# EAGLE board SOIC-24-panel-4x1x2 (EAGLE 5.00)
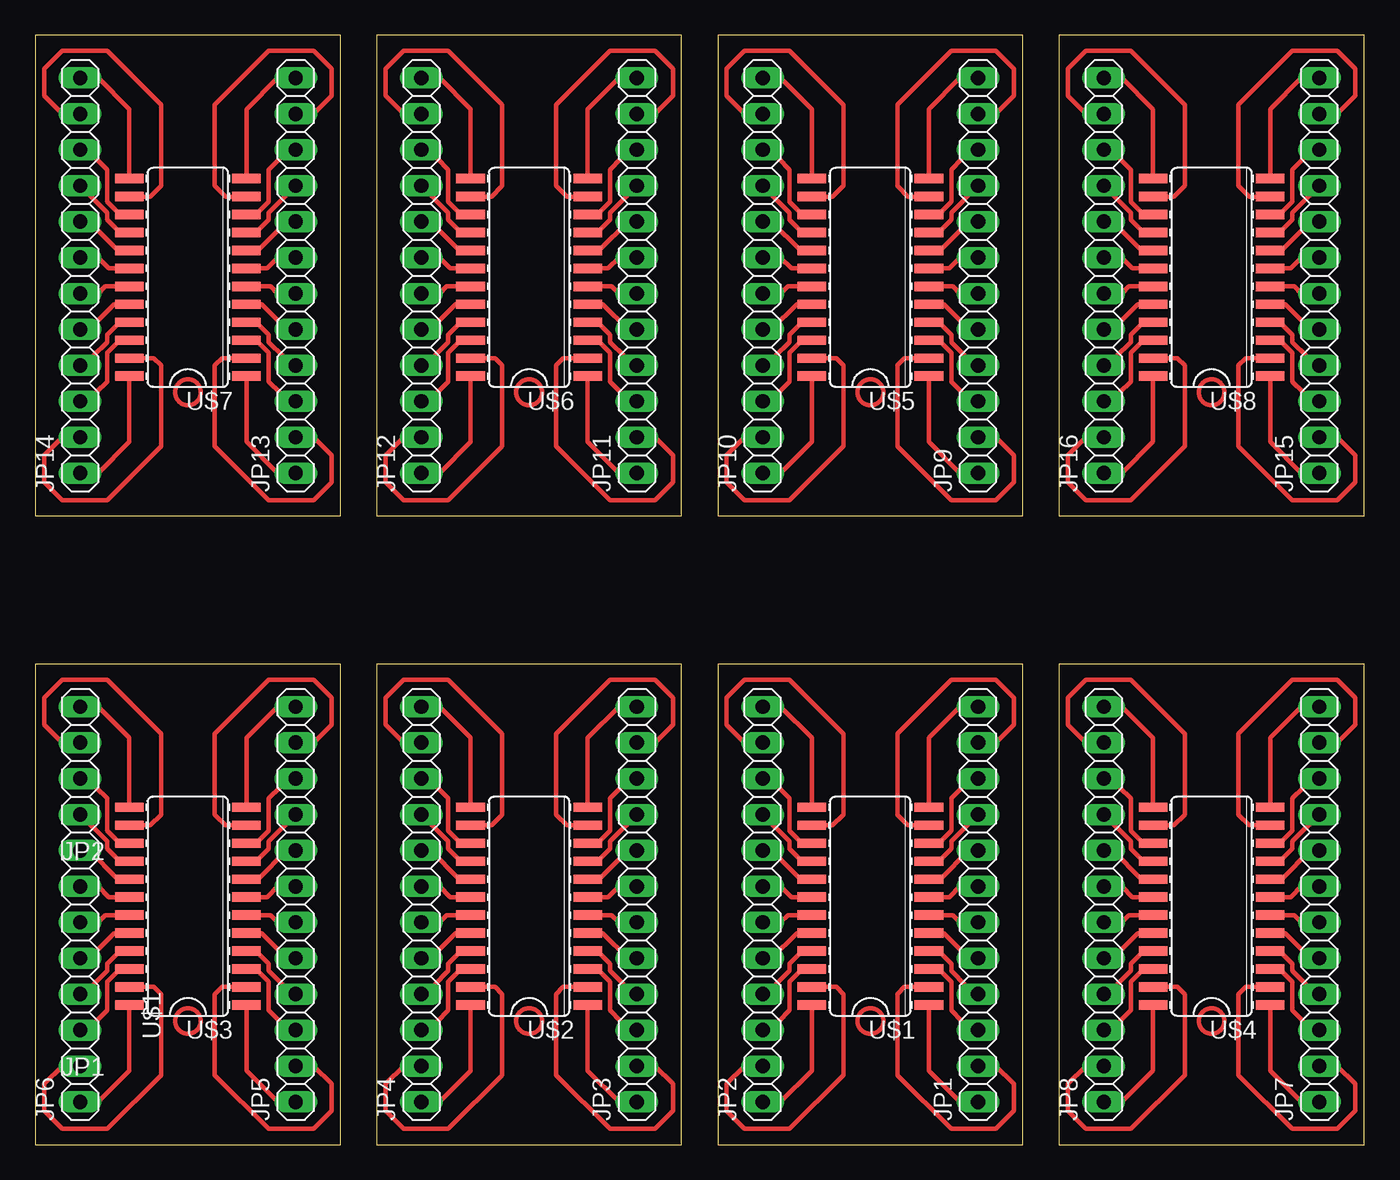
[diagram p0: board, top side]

Size 93.97 x 78.41 mm. Coordinates in mm from the lower left corner, seen from the top.
Outline: 69.84,0 69.84,33.96 48.26,33.96 48.26,0 69.84,0
Outline: 45.71,0 45.71,33.96 24.13,33.96 24.13,0 45.71,0
Outline: 21.58,0 21.58,33.96 0,33.96 0,0 21.58,0
Outline: 93.97,0 93.97,33.96 72.39,33.96 72.39,0 93.97,0
Outline: 69.84,44.45 69.84,78.41 48.26,78.41 48.26,44.45 69.84,44.45
Outline: 45.71,44.45 45.71,78.41 24.13,78.41 24.13,44.45 45.71,44.45
Outline: 21.58,44.45 21.58,78.41 0,78.41 0,44.45 21.58,44.45
Outline: 93.97,44.45 93.97,78.41 72.39,78.41 72.39,44.45 93.97,44.45
Copper layers (1*16): Top 0.035mm / dielectric 1.5mm / Bottom 0.035mm
Design rules "default": minimum track width 10mil, minimum drill 24mil, track to track 8mil, track to pad 8mil, pad to pad 8mil, via to via 8mil, smd to smd 8mil, copper to edge 40mil, drill to drill 8mil, minimum pad ring 10mil, minimum via ring 8mil, stop-mask expansion 4mil, vias tented up to drill 0mil, thermal gap 10mil

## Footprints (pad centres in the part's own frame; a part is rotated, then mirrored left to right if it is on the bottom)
1X12 = drill 1.016 long: 1 -13.97,0; 2 -11.43,0; 3 -8.89,0; 4 -6.35,0; 5 -3.81,0; 6 -1.27,0; 7 1.27,0; 8 3.81,0; 9 6.35,0; 10 8.89,0; 11 11.43,0; 12 13.97,0
SOIC-24 = smd 0.66 x 2.032: 1 -6.985,-4.14; 2 -5.715,-4.14; 3 -4.445,-4.14; 4 -3.175,-4.14; 5 -1.905,-4.14; 6 -0.635,-4.14; 7 0.635,-4.14; 8 1.905,-4.14; 9 3.175,-4.14; 10 4.445,-4.14; 11 5.715,-4.14; 12 6.985,-4.14; 13 6.985,4.14; 14 5.715,4.14; 15 4.445,4.14; 16 3.175,4.14; 17 1.905,4.14; 18 0.635,4.14; 19 -0.635,4.14; 20 -1.905,4.14; 21 -3.175,4.14; 22 -4.445,4.14; 23 -5.715,4.14; 24 -6.985,4.14

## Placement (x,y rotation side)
JP1  [1X12]  66.67,16.98 90 top
JP2  [1X12]  51.43,16.98 90 top
JP3  [1X12]  42.54,16.98 90 top
JP4  [1X12]  27.3,16.98 90 top
JP5  [1X12]  18.41,16.98 90 top
JP6  [1X12]  3.17,16.98 90 top
JP7  [1X12]  90.8,16.98 90 top
JP8  [1X12]  75.56,16.98 90 top
JP9  [1X12]  66.67,61.43 90 top
JP10  [1X12]  51.43,61.43 90 top
JP11  [1X12]  42.54,61.43 90 top
JP12  [1X12]  27.3,61.43 90 top
JP13  [1X12]  18.41,61.43 90 top
JP14  [1X12]  3.17,61.43 90 top
JP15  [1X12]  90.8,61.43 90 top
JP16  [1X12]  75.56,61.43 90 top
U$1  SOIC-24  [SOIC-24]  59.05,16.85 90 top
U$2  SOIC-24  [SOIC-24]  34.92,16.85 90 top
U$3  SOIC-24  [SOIC-24]  10.79,16.85 90 top
U$4  SOIC-24  [SOIC-24]  83.18,16.85 90 top
U$5  SOIC-24  [SOIC-24]  59.05,61.3 90 top
U$6  SOIC-24  [SOIC-24]  34.92,61.3 90 top
U$7  SOIC-24  [SOIC-24]  10.79,61.3 90 top
U$8  SOIC-24  [SOIC-24]  83.18,61.3 90 top

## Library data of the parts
JP1-JP16 = pinhead
U$1-U$8 = smd

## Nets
N$1: JP1.1 U$1.1
N$2: JP1.2 U$1.2
N$3: JP1.3 U$1.3
N$4: JP1.4 U$1.4
N$5: JP1.5 U$1.5
N$6: JP1.6 U$1.6
N$7: JP1.7 U$1.7
N$8: JP1.8 U$1.8
N$9: JP1.9 U$1.9
N$10: JP1.10 U$1.10
N$11: JP1.11 U$1.11
N$12: JP1.12 U$1.12
N$13: JP2.1 U$1.24
N$14: JP2.2 U$1.23
N$15: JP2.3 U$1.22
N$16: JP2.4 U$1.21
N$17: JP2.5 U$1.20
N$18: JP2.6 U$1.19
N$19: JP2.7 U$1.18
N$20: JP2.8 U$1.17
N$21: JP2.9 U$1.16
N$22: JP2.10 U$1.15
N$23: JP2.11 U$1.14
N$24: JP2.12 U$1.13
N$25: JP3.1 U$2.1
N$26: JP3.2 U$2.2
N$27: JP3.3 U$2.3
N$28: JP3.4 U$2.4
N$29: JP3.5 U$2.5
N$30: JP3.6 U$2.6
N$31: JP3.7 U$2.7
N$32: JP3.8 U$2.8
N$33: JP3.9 U$2.9
N$34: JP3.10 U$2.10
N$35: JP3.11 U$2.11
N$36: JP3.12 U$2.12
N$37: JP4.1 U$2.24
N$38: JP4.2 U$2.23
N$39: JP4.3 U$2.22
N$40: JP4.4 U$2.21
N$41: JP4.5 U$2.20
N$42: JP4.6 U$2.19
N$43: JP4.7 U$2.18
N$44: JP4.8 U$2.17
N$45: JP4.9 U$2.16
N$46: JP4.10 U$2.15
N$47: JP4.11 U$2.14
N$48: JP4.12 U$2.13
N$49: JP5.1 U$3.1
N$50: JP5.2 U$3.2
N$51: JP5.3 U$3.3
N$52: JP5.4 U$3.4
N$53: JP5.5 U$3.5
N$54: JP5.6 U$3.6
N$55: JP5.7 U$3.7
N$56: JP5.8 U$3.8
N$57: JP5.9 U$3.9
N$58: JP5.10 U$3.10
N$59: JP5.11 U$3.11
N$60: JP5.12 U$3.12
N$61: JP6.1 U$3.24
N$62: JP6.2 U$3.23
N$63: JP6.3 U$3.22
N$64: JP6.4 U$3.21
N$65: JP6.5 U$3.20
N$66: JP6.6 U$3.19
N$67: JP6.7 U$3.18
N$68: JP6.8 U$3.17
N$69: JP6.9 U$3.16
N$70: JP6.10 U$3.15
N$71: JP6.11 U$3.14
N$72: JP6.12 U$3.13
N$73: JP7.1 U$4.1
N$74: JP7.2 U$4.2
N$75: JP7.3 U$4.3
N$76: JP7.4 U$4.4
N$77: JP7.5 U$4.5
N$78: JP7.6 U$4.6
N$79: JP7.7 U$4.7
N$80: JP7.8 U$4.8
N$81: JP7.9 U$4.9
N$82: JP7.10 U$4.10
N$83: JP7.11 U$4.11
N$84: JP7.12 U$4.12
N$85: JP8.1 U$4.24
N$86: JP8.2 U$4.23
N$87: JP8.3 U$4.22
N$88: JP8.4 U$4.21
N$89: JP8.5 U$4.20
N$90: JP8.6 U$4.19
N$91: JP8.7 U$4.18
N$92: JP8.8 U$4.17
N$93: JP8.9 U$4.16
N$94: JP8.10 U$4.15
N$95: JP8.11 U$4.14
N$96: JP8.12 U$4.13
N$97: JP9.1 U$5.1
N$98: JP9.2 U$5.2
N$99: JP9.3 U$5.3
N$100: JP9.4 U$5.4
N$101: JP9.5 U$5.5
N$102: JP9.6 U$5.6
N$103: JP9.7 U$5.7
N$104: JP9.8 U$5.8
N$105: JP9.9 U$5.9
N$106: JP9.10 U$5.10
N$107: JP9.11 U$5.11
N$108: JP9.12 U$5.12
N$109: JP10.1 U$5.24
N$110: JP10.2 U$5.23
N$111: JP10.3 U$5.22
N$112: JP10.4 U$5.21
N$113: JP10.5 U$5.20
N$114: JP10.6 U$5.19
N$115: JP10.7 U$5.18
N$116: JP10.8 U$5.17
N$117: JP10.9 U$5.16
N$118: JP10.10 U$5.15
N$119: JP10.11 U$5.14
N$120: JP10.12 U$5.13
N$121: JP11.1 U$6.1
N$122: JP11.2 U$6.2
N$123: JP11.3 U$6.3
N$124: JP11.4 U$6.4
N$125: JP11.5 U$6.5
N$126: JP11.6 U$6.6
N$127: JP11.7 U$6.7
N$128: JP11.8 U$6.8
N$129: JP11.9 U$6.9
N$130: JP11.10 U$6.10
N$131: JP11.11 U$6.11
N$132: JP11.12 U$6.12
N$133: JP12.1 U$6.24
N$134: JP12.2 U$6.23
N$135: JP12.3 U$6.22
N$136: JP12.4 U$6.21
N$137: JP12.5 U$6.20
N$138: JP12.6 U$6.19
N$139: JP12.7 U$6.18
N$140: JP12.8 U$6.17
N$141: JP12.9 U$6.16
N$142: JP12.10 U$6.15
N$143: JP12.11 U$6.14
N$144: JP12.12 U$6.13
N$145: JP13.1 U$7.1
N$146: JP13.2 U$7.2
N$147: JP13.3 U$7.3
N$148: JP13.4 U$7.4
N$149: JP13.5 U$7.5
N$150: JP13.6 U$7.6
N$151: JP13.7 U$7.7
N$152: JP13.8 U$7.8
N$153: JP13.9 U$7.9
N$154: JP13.10 U$7.10
N$155: JP13.11 U$7.11
N$156: JP13.12 U$7.12
N$157: JP14.1 U$7.24
N$158: JP14.2 U$7.23
N$159: JP14.3 U$7.22
N$160: JP14.4 U$7.21
N$161: JP14.5 U$7.20
N$162: JP14.6 U$7.19
N$163: JP14.7 U$7.18
N$164: JP14.8 U$7.17
N$165: JP14.9 U$7.16
N$166: JP14.10 U$7.15
N$167: JP14.11 U$7.14
N$168: JP14.12 U$7.13
N$169: JP15.1 U$8.1
N$170: JP15.2 U$8.2
N$171: JP15.3 U$8.3
N$172: JP15.4 U$8.4
N$173: JP15.5 U$8.5
N$174: JP15.6 U$8.6
N$175: JP15.7 U$8.7
N$176: JP15.8 U$8.8
N$177: JP15.9 U$8.9
N$178: JP15.10 U$8.10
N$179: JP15.11 U$8.11
N$180: JP15.12 U$8.12
N$181: JP16.1 U$8.24
N$182: JP16.2 U$8.23
N$183: JP16.3 U$8.22
N$184: JP16.4 U$8.21
N$185: JP16.5 U$8.20
N$186: JP16.6 U$8.19
N$187: JP16.7 U$8.18
N$188: JP16.8 U$8.17
N$189: JP16.9 U$8.16
N$190: JP16.10 U$8.15
N$191: JP16.11 U$8.14
N$192: JP16.12 U$8.13

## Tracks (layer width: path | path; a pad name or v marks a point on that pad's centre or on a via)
N$1
  Top 0.305: U$1.1 63.19,5.22 65.4,3.01 JP1.1
N$2
  Top 0.305: U$1.2 61.46,11.14 60.96,10.63 60.96,4.92 64.77,1.1 67.94,1.1 69.21,2.38 69.21,4.28 67.94,5.55 JP1.2
N$3
  Top 0.254: 64.13,12.15 U$1.3
  Top 0.305: 64.13,12.15 64.77,11.52 64.77,9.49 65.53,8.73 JP1.3
N$4
  Top 0.254: 64.13,13.42 U$1.4
  Top 0.305: 64.13,13.42 64.77,12.79 64.77,12.28 65.78,11.27 JP1.4
N$5
  Top 0.305: U$1.5 64.26,14.95 66.03,13.17 JP1.5
N$6
  Top 0.305: U$1.6 64.89,16.22 65.4,15.71 JP1.6
N$7
  Top 0.305: U$1.7 64.64,17.49 65.4,18.25 JP1.7
N$8
  Top 0.305: 64,18.76 66.03,20.79 JP1.8
  Top 0.406: U$1.8 64,18.76
N$9
  Top 0.254: U$1.9 64.13,20.28
  Top 0.305: 64.13,20.28 64.77,20.92 64.77,21.42 JP1.9
N$10
  Top 0.254: 64.13,21.55 U$1.10
  Top 0.305: 64.13,21.55 64.77,22.19 64.77,24.47 65.53,25.23 JP1.10
N$11
  Top 0.305: U$1.11 61.72,22.57 60.96,23.33 60.96,29.04 64.77,32.85 67.94,32.85 69.21,31.58 69.21,29.68 67.94,28.41 JP1.11
N$12
  Top 0.305: U$1.12 63.19,28.74 65.4,30.95 JP1.12
N$13
  Top 0.305: U$1.24 54.91,5.22 52.7,3.01 JP2.1
N$14
  Top 0.305: U$1.23 56.64,11.14 57.15,10.63 57.15,4.92 53.34,1.1 50.16,1.1 48.89,2.38 48.89,4.28 50.16,5.55 JP2.2
N$15
  Top 0.254: U$1.22 53.97,12.15
  Top 0.305: 53.97,12.15 53.34,11.52 53.34,9.49 52.57,8.73 JP2.3
N$16
  Top 0.254: U$1.21 53.97,13.42
  Top 0.305: 53.97,13.42 53.34,12.79 53.34,12.28 52.32,11.27 JP2.4
N$17
  Top 0.305: U$1.20 53.84,14.95 52.07,13.17 JP2.5
N$18
  Top 0.305: U$1.19 53.21,16.22 52.7,15.71 JP2.6
N$19
  Top 0.305: U$1.18 53.46,17.49 52.7,18.25 JP2.7
N$20
  Top 0.305: U$1.17 54.1,18.76 52.07,20.79 JP2.8
N$21
  Top 0.254: U$1.16 53.97,20.28
  Top 0.305: 53.97,20.28 53.34,20.92 53.34,21.42 JP2.9
N$22
  Top 0.254: U$1.15 53.97,21.55
  Top 0.305: 53.97,21.55 53.34,22.19 53.34,24.47 52.57,25.23 JP2.10
N$23
  Top 0.305: U$1.14 56.38,22.57 57.15,23.33 57.15,29.04 53.34,32.85 50.16,32.85 48.89,31.58 48.89,29.68 50.16,28.41
  Top 0.406: 50.16,28.41 JP2.11
N$24
  Top 0.305: U$1.13 54.91,28.74 52.7,30.95 JP2.12
N$25
  Top 0.305: U$2.1 39.06,5.22 41.27,3.01 JP3.1
N$26
  Top 0.305: U$2.2 37.33,11.14 36.83,10.63 36.83,4.92 40.64,1.1 43.81,1.1 45.08,2.38 45.08,4.28 43.81,5.55 JP3.2
N$27
  Top 0.254: 40,12.15 U$2.3
  Top 0.305: 40,12.15 40.64,11.52 40.64,9.49 41.4,8.73 JP3.3
N$28
  Top 0.254: 40,13.42 U$2.4
  Top 0.305: 40,13.42 40.64,12.79 40.64,12.28 41.65,11.27 JP3.4
N$29
  Top 0.305: U$2.5 40.13,14.95 41.91,13.17 JP3.5
N$30
  Top 0.305: U$2.6 40.76,16.22 41.27,15.71 JP3.6
N$31
  Top 0.305: U$2.7 40.51,17.49 41.27,18.25 JP3.7
N$32
  Top 0.305: 39.87,18.76 41.91,20.79 JP3.8
  Top 0.406: U$2.8 39.87,18.76
N$33
  Top 0.254: U$2.9 40,20.28
  Top 0.305: 40,20.28 40.64,20.92 40.64,21.42 JP3.9
N$34
  Top 0.254: 40,21.55 U$2.10
  Top 0.305: 40,21.55 40.64,22.19 40.64,24.47 41.4,25.23 JP3.10
N$35
  Top 0.305: U$2.11 37.59,22.57 36.83,23.33 36.83,29.04 40.64,32.85 43.81,32.85 45.08,31.58 45.08,29.68 43.81,28.41 JP3.11
N$36
  Top 0.305: U$2.12 39.06,28.74 41.27,30.95 JP3.12
N$37
  Top 0.305: U$2.24 30.78,5.22 28.57,3.01 JP4.1
N$38
  Top 0.305: U$2.23 32.51,11.14 33.02,10.63 33.02,4.92 29.2,1.1 26.03,1.1 24.76,2.38 24.76,4.28 26.03,5.55 JP4.2
N$39
  Top 0.254: U$2.22 29.84,12.15
  Top 0.305: 29.84,12.15 29.2,11.52 29.2,9.49 28.44,8.73 JP4.3
N$40
  Top 0.254: U$2.21 29.84,13.42
  Top 0.305: 29.84,13.42 29.2,12.79 29.2,12.28 28.19,11.27 JP4.4
N$41
  Top 0.305: U$2.20 29.71,14.95 27.93,13.17 JP4.5
N$42
  Top 0.305: U$2.19 29.08,16.22 28.57,15.71 JP4.6
N$43
  Top 0.305: U$2.18 29.33,17.49 28.57,18.25 JP4.7
N$44
  Top 0.305: U$2.17 29.97,18.76 27.93,20.79 JP4.8
N$45
  Top 0.254: U$2.16 29.84,20.28
  Top 0.305: 29.84,20.28 29.2,20.92 29.2,21.42 JP4.9
N$46
  Top 0.254: U$2.15 29.84,21.55
  Top 0.305: 29.84,21.55 29.2,22.19 29.2,24.47 28.44,25.23 JP4.10
N$47
  Top 0.305: U$2.14 32.25,22.57 33.02,23.33 33.02,29.04 29.2,32.85 26.03,32.85 24.76,31.58 24.76,29.68 26.03,28.41
  Top 0.406: 26.03,28.41 JP4.11
N$48
  Top 0.305: U$2.13 30.78,28.74 28.57,30.95 JP4.12
N$49
  Top 0.305: U$3.1 14.93,5.22 17.14,3.01 JP5.1
N$50
  Top 0.305: U$3.2 13.2,11.14 12.7,10.63 12.7,4.92 16.5,1.1 19.68,1.1 20.95,2.38 20.95,4.28 19.68,5.55 JP5.2
N$51
  Top 0.254: 15.87,12.15 U$3.3
  Top 0.305: 15.87,12.15 16.5,11.52 16.5,9.49 17.27,8.73 JP5.3
N$52
  Top 0.254: 15.87,13.42 U$3.4
  Top 0.305: 15.87,13.42 16.5,12.79 16.5,12.28 17.52,11.27 JP5.4
N$53
  Top 0.305: U$3.5 16,14.95 17.77,13.17 JP5.5
N$54
  Top 0.305: U$3.6 16.63,16.22 17.14,15.71 JP5.6
N$55
  Top 0.305: U$3.7 16.38,17.49 17.14,18.25 JP5.7
N$56
  Top 0.305: 15.74,18.76 17.77,20.79 JP5.8
  Top 0.406: U$3.8 15.74,18.76
N$57
  Top 0.254: U$3.9 15.87,20.28
  Top 0.305: 15.87,20.28 16.5,20.92 16.5,21.42 JP5.9
N$58
  Top 0.254: 15.87,21.55 U$3.10
  Top 0.305: 15.87,21.55 16.5,22.19 16.5,24.47 17.27,25.23 JP5.10
N$59
  Top 0.305: U$3.11 13.46,22.57 12.7,23.33 12.7,29.04 16.5,32.85 19.68,32.85 20.95,31.58 20.95,29.68 19.68,28.41 JP5.11
N$60
  Top 0.305: U$3.12 14.93,28.74 17.14,30.95 JP5.12
N$61
  Top 0.305: U$3.24 6.65,5.22 4.44,3.01 JP6.1
N$62
  Top 0.305: U$3.23 8.38,11.14 8.89,10.63 8.89,4.92 5.08,1.1 1.9,1.1 0.63,2.38 0.63,4.28 1.9,5.55 JP6.2
N$63
  Top 0.254: U$3.22 5.71,12.15
  Top 0.305: 5.71,12.15 5.08,11.52 5.08,9.49 4.31,8.73 JP6.3
N$64
  Top 0.254: U$3.21 5.71,13.42
  Top 0.305: 5.71,13.42 5.08,12.79 5.08,12.28 4.06,11.27 JP6.4
N$65
  Top 0.305: U$3.20 5.58,14.95 3.8,13.17 JP6.5
N$66
  Top 0.305: U$3.19 4.95,16.22 4.44,15.71 JP6.6
N$67
  Top 0.305: U$3.18 5.2,17.49 4.44,18.25 JP6.7
N$68
  Top 0.305: U$3.17 5.84,18.76 3.8,20.79 JP6.8
N$69
  Top 0.254: U$3.16 5.71,20.28
  Top 0.305: 5.71,20.28 5.08,20.92 5.08,21.42 JP6.9
N$70
  Top 0.254: U$3.15 5.71,21.55
  Top 0.305: 5.71,21.55 5.08,22.19 5.08,24.47 4.31,25.23 JP6.10
N$71
  Top 0.305: U$3.14 8.12,22.57 8.89,23.33 8.89,29.04 5.08,32.85 1.9,32.85 0.63,31.58 0.63,29.68 1.9,28.41
  Top 0.406: 1.9,28.41 JP6.11
N$72
  Top 0.305: U$3.13 6.65,28.74 4.44,30.95 JP6.12
N$73
  Top 0.305: U$4.1 87.32,5.22 89.53,3.01 JP7.1
N$74
  Top 0.305: U$4.2 85.59,11.14 85.08,10.63 85.08,4.92 88.89,1.1 92.07,1.1 93.34,2.38 93.34,4.28 92.07,5.55 JP7.2
N$75
  Top 0.254: 88.26,12.15 U$4.3
  Top 0.305: 88.26,12.15 88.89,11.52 88.89,9.49 89.66,8.73 JP7.3
N$76
  Top 0.254: 88.26,13.42 U$4.4
  Top 0.305: 88.26,13.42 88.89,12.79 88.89,12.28 89.91,11.27 JP7.4
N$77
  Top 0.305: U$4.5 88.39,14.95 90.16,13.17 JP7.5
N$78
  Top 0.305: U$4.6 89.02,16.22 89.53,15.71 JP7.6
N$79
  Top 0.305: U$4.7 88.77,17.49 89.53,18.25 JP7.7
N$80
  Top 0.305: 88.13,18.76 90.16,20.79 JP7.8
  Top 0.406: U$4.8 88.13,18.76
N$81
  Top 0.254: U$4.9 88.26,20.28
  Top 0.305: 88.26,20.28 88.89,20.92 88.89,21.42 JP7.9
N$82
  Top 0.254: 88.26,21.55 U$4.10
  Top 0.305: 88.26,21.55 88.89,22.19 88.89,24.47 89.66,25.23 JP7.10
N$83
  Top 0.305: U$4.11 85.85,22.57 85.08,23.33 85.08,29.04 88.89,32.85 92.07,32.85 93.34,31.58 93.34,29.68 92.07,28.41 JP7.11
N$84
  Top 0.305: U$4.12 87.32,28.74 89.53,30.95 JP7.12
N$85
  Top 0.305: U$4.24 79.04,5.22 76.83,3.01 JP8.1
N$86
  Top 0.305: U$4.23 80.77,11.14 81.27,10.63 81.27,4.92 77.46,1.1 74.29,1.1 73.02,2.38 73.02,4.28 74.29,5.55 JP8.2
N$87
  Top 0.254: U$4.22 78.1,12.15
  Top 0.305: 78.1,12.15 77.46,11.52 77.46,9.49 76.7,8.73 JP8.3
N$88
  Top 0.254: U$4.21 78.1,13.42
  Top 0.305: 78.1,13.42 77.46,12.79 77.46,12.28 76.45,11.27 JP8.4
N$89
  Top 0.305: U$4.20 77.97,14.95 76.19,13.17 JP8.5
N$90
  Top 0.305: U$4.19 77.34,16.22 76.83,15.71 JP8.6
N$91
  Top 0.305: U$4.18 77.59,17.49 76.83,18.25 JP8.7
N$92
  Top 0.305: U$4.17 78.23,18.76 76.19,20.79 JP8.8
N$93
  Top 0.254: U$4.16 78.1,20.28
  Top 0.305: 78.1,20.28 77.46,20.92 77.46,21.42 JP8.9
N$94
  Top 0.254: U$4.15 78.1,21.55
  Top 0.305: 78.1,21.55 77.46,22.19 77.46,24.47 76.7,25.23 JP8.10
N$95
  Top 0.305: U$4.14 80.51,22.57 81.27,23.33 81.27,29.04 77.46,32.85 74.29,32.85 73.02,31.58 73.02,29.68 74.29,28.41
  Top 0.406: 74.29,28.41 JP8.11
N$96
  Top 0.305: U$4.13 79.04,28.74 76.83,30.95 JP8.12
N$97
  Top 0.305: U$5.1 63.19,49.67 65.4,47.46 JP9.1
N$98
  Top 0.305: U$5.2 61.46,55.59 60.96,55.08 60.96,49.37 64.77,45.55 67.94,45.55 69.21,46.82 69.21,48.73 67.94,50 JP9.2
N$99
  Top 0.254: 64.13,56.6 U$5.3
  Top 0.305: 64.13,56.6 64.77,55.97 64.77,53.94 65.53,53.17 JP9.3
N$100
  Top 0.254: 64.13,57.87 U$5.4
  Top 0.305: 64.13,57.87 64.77,57.24 64.77,56.73 65.78,55.71 JP9.4
N$101
  Top 0.305: U$5.5 64.26,59.4 66.03,57.62 JP9.5
N$102
  Top 0.305: U$5.6 64.89,60.67 65.4,60.16 JP9.6
N$103
  Top 0.305: U$5.7 64.64,61.94 65.4,62.7 JP9.7
N$104
  Top 0.305: 64,63.21 66.03,65.24 JP9.8
  Top 0.406: U$5.8 64,63.21
N$105
  Top 0.254: U$5.9 64.13,64.73
  Top 0.305: 64.13,64.73 64.77,65.37 64.77,65.88 JP9.9
N$106
  Top 0.254: 64.13,66 U$5.10
  Top 0.305: 64.13,66 64.77,66.64 64.77,68.92 65.53,69.69 JP9.10
N$107
  Top 0.305: U$5.11 61.72,67.02 60.96,67.78 60.96,73.5 64.77,77.3 67.94,77.3 69.21,76.03 69.21,74.13 67.94,72.86 JP9.11
N$108
  Top 0.305: U$5.12 63.19,73.19 65.4,75.4 JP9.12
N$109
  Top 0.305: U$5.24 54.91,49.67 52.7,47.46 JP10.1
N$110
  Top 0.305: U$5.23 56.64,55.59 57.15,55.08 57.15,49.37 53.34,45.55 50.16,45.55 48.89,46.82 48.89,48.73 50.16,50 JP10.2
N$111
  Top 0.254: U$5.22 53.97,56.6
  Top 0.305: 53.97,56.6 53.34,55.97 53.34,53.94 52.57,53.17 JP10.3
N$112
  Top 0.254: U$5.21 53.97,57.87
  Top 0.305: 53.97,57.87 53.34,57.24 53.34,56.73 52.32,55.71 JP10.4
N$113
  Top 0.305: U$5.20 53.84,59.4 52.07,57.62 JP10.5
N$114
  Top 0.305: U$5.19 53.21,60.67 52.7,60.16 JP10.6
N$115
  Top 0.305: U$5.18 53.46,61.94 52.7,62.7 JP10.7
N$116
  Top 0.305: U$5.17 54.1,63.21 52.07,65.24 JP10.8
N$117
  Top 0.254: U$5.16 53.97,64.73
  Top 0.305: 53.97,64.73 53.34,65.37 53.34,65.88 JP10.9
N$118
  Top 0.254: U$5.15 53.97,66
  Top 0.305: 53.97,66 53.34,66.64 53.34,68.92 52.57,69.69 JP10.10
N$119
  Top 0.305: U$5.14 56.38,67.02 57.15,67.78 57.15,73.5 53.34,77.3 50.16,77.3 48.89,76.03 48.89,74.13 50.16,72.86
  Top 0.406: 50.16,72.86 JP10.11
N$120
  Top 0.305: U$5.13 54.91,73.19 52.7,75.4 JP10.12
N$121
  Top 0.305: U$6.1 39.06,49.67 41.27,47.46 JP11.1
N$122
  Top 0.305: U$6.2 37.33,55.59 36.83,55.08 36.83,49.37 40.64,45.55 43.81,45.55 45.08,46.82 45.08,48.73 43.81,50 JP11.2
N$123
  Top 0.254: 40,56.6 U$6.3
  Top 0.305: 40,56.6 40.64,55.97 40.64,53.94 41.4,53.17 JP11.3
N$124
  Top 0.254: 40,57.87 U$6.4
  Top 0.305: 40,57.87 40.64,57.24 40.64,56.73 41.65,55.71 JP11.4
N$125
  Top 0.305: U$6.5 40.13,59.4 41.91,57.62 JP11.5
N$126
  Top 0.305: U$6.6 40.76,60.67 41.27,60.16 JP11.6
N$127
  Top 0.305: U$6.7 40.51,61.94 41.27,62.7 JP11.7
N$128
  Top 0.305: 39.87,63.21 41.91,65.24 JP11.8
  Top 0.406: U$6.8 39.87,63.21
N$129
  Top 0.254: U$6.9 40,64.73
  Top 0.305: 40,64.73 40.64,65.37 40.64,65.88 JP11.9
N$130
  Top 0.254: 40,66 U$6.10
  Top 0.305: 40,66 40.64,66.64 40.64,68.92 41.4,69.69 JP11.10
N$131
  Top 0.305: U$6.11 37.59,67.02 36.83,67.78 36.83,73.5 40.64,77.3 43.81,77.3 45.08,76.03 45.08,74.13 43.81,72.86 JP11.11
N$132
  Top 0.305: U$6.12 39.06,73.19 41.27,75.4 JP11.12
N$133
  Top 0.305: U$6.24 30.78,49.67 28.57,47.46 JP12.1
N$134
  Top 0.305: U$6.23 32.51,55.59 33.02,55.08 33.02,49.37 29.2,45.55 26.03,45.55 24.76,46.82 24.76,48.73 26.03,50 JP12.2
N$135
  Top 0.254: U$6.22 29.84,56.6
  Top 0.305: 29.84,56.6 29.2,55.97 29.2,53.94 28.44,53.17 JP12.3
N$136
  Top 0.254: U$6.21 29.84,57.87
  Top 0.305: 29.84,57.87 29.2,57.24 29.2,56.73 28.19,55.71 JP12.4
N$137
  Top 0.305: U$6.20 29.71,59.4 27.93,57.62 JP12.5
N$138
  Top 0.305: U$6.19 29.08,60.67 28.57,60.16 JP12.6
N$139
  Top 0.305: U$6.18 29.33,61.94 28.57,62.7 JP12.7
N$140
  Top 0.305: U$6.17 29.97,63.21 27.93,65.24 JP12.8
N$141
  Top 0.254: U$6.16 29.84,64.73
  Top 0.305: 29.84,64.73 29.2,65.37 29.2,65.88 JP12.9
N$142
  Top 0.254: U$6.15 29.84,66
  Top 0.305: 29.84,66 29.2,66.64 29.2,68.92 28.44,69.69 JP12.10
N$143
  Top 0.305: U$6.14 32.25,67.02 33.02,67.78 33.02,73.5 29.2,77.3 26.03,77.3 24.76,76.03 24.76,74.13 26.03,72.86
  Top 0.406: 26.03,72.86 JP12.11
N$144
  Top 0.305: U$6.13 30.78,73.19 28.57,75.4 JP12.12
N$145
  Top 0.305: U$7.1 14.93,49.67 17.14,47.46 JP13.1
N$146
  Top 0.305: U$7.2 13.2,55.59 12.7,55.08 12.7,49.37 16.5,45.55 19.68,45.55 20.95,46.82 20.95,48.73 19.68,50 JP13.2
N$147
  Top 0.254: 15.87,56.6 U$7.3
  Top 0.305: 15.87,56.6 16.5,55.97 16.5,53.94 17.27,53.17 JP13.3
N$148
  Top 0.254: 15.87,57.87 U$7.4
  Top 0.305: 15.87,57.87 16.5,57.24 16.5,56.73 17.52,55.71 JP13.4
N$149
  Top 0.305: U$7.5 16,59.4 17.77,57.62 JP13.5
N$150
  Top 0.305: U$7.6 16.63,60.67 17.14,60.16 JP13.6
N$151
  Top 0.305: U$7.7 16.38,61.94 17.14,62.7 JP13.7
N$152
  Top 0.305: 15.74,63.21 17.77,65.24 JP13.8
  Top 0.406: U$7.8 15.74,63.21
N$153
  Top 0.254: U$7.9 15.87,64.73
  Top 0.305: 15.87,64.73 16.5,65.37 16.5,65.88 JP13.9
N$154
  Top 0.254: 15.87,66 U$7.10
  Top 0.305: 15.87,66 16.5,66.64 16.5,68.92 17.27,69.69 JP13.10
N$155
  Top 0.305: U$7.11 13.46,67.02 12.7,67.78 12.7,73.5 16.5,77.3 19.68,77.3 20.95,76.03 20.95,74.13 19.68,72.86 JP13.11
N$156
  Top 0.305: U$7.12 14.93,73.19 17.14,75.4 JP13.12
N$157
  Top 0.305: U$7.24 6.65,49.67 4.44,47.46 JP14.1
N$158
  Top 0.305: U$7.23 8.38,55.59 8.89,55.08 8.89,49.37 5.08,45.55 1.9,45.55 0.63,46.82 0.63,48.73 1.9,50 JP14.2
N$159
  Top 0.254: U$7.22 5.71,56.6
  Top 0.305: 5.71,56.6 5.08,55.97 5.08,53.94 4.31,53.17 JP14.3
N$160
  Top 0.254: U$7.21 5.71,57.87
  Top 0.305: 5.71,57.87 5.08,57.24 5.08,56.73 4.06,55.71 JP14.4
N$161
  Top 0.305: U$7.20 5.58,59.4 3.8,57.62 JP14.5
N$162
  Top 0.305: U$7.19 4.95,60.67 4.44,60.16 JP14.6
N$163
  Top 0.305: U$7.18 5.2,61.94 4.44,62.7 JP14.7
N$164
  Top 0.305: U$7.17 5.84,63.21 3.8,65.24 JP14.8
N$165
  Top 0.254: U$7.16 5.71,64.73
  Top 0.305: 5.71,64.73 5.08,65.37 5.08,65.88 JP14.9
N$166
  Top 0.254: U$7.15 5.71,66
  Top 0.305: 5.71,66 5.08,66.64 5.08,68.92 4.31,69.69 JP14.10
N$167
  Top 0.305: U$7.14 8.12,67.02 8.89,67.78 8.89,73.5 5.08,77.3 1.9,77.3 0.63,76.03 0.63,74.13 1.9,72.86
  Top 0.406: 1.9,72.86 JP14.11
N$168
  Top 0.305: U$7.13 6.65,73.19 4.44,75.4 JP14.12
N$169
  Top 0.305: U$8.1 87.32,49.67 89.53,47.46 JP15.1
N$170
  Top 0.305: U$8.2 85.59,55.59 85.08,55.08 85.08,49.37 88.89,45.55 92.07,45.55 93.34,46.82 93.34,48.73 92.07,50 JP15.2
N$171
  Top 0.254: 88.26,56.6 U$8.3
  Top 0.305: 88.26,56.6 88.89,55.97 88.89,53.94 89.66,53.17 JP15.3
N$172
  Top 0.254: 88.26,57.87 U$8.4
  Top 0.305: 88.26,57.87 88.89,57.24 88.89,56.73 89.91,55.71 JP15.4
N$173
  Top 0.305: U$8.5 88.39,59.4 90.16,57.62 JP15.5
N$174
  Top 0.305: U$8.6 89.02,60.67 89.53,60.16 JP15.6
N$175
  Top 0.305: U$8.7 88.77,61.94 89.53,62.7 JP15.7
N$176
  Top 0.305: 88.13,63.21 90.16,65.24 JP15.8
  Top 0.406: U$8.8 88.13,63.21
N$177
  Top 0.254: U$8.9 88.26,64.73
  Top 0.305: 88.26,64.73 88.89,65.37 88.89,65.88 JP15.9
N$178
  Top 0.254: 88.26,66 U$8.10
  Top 0.305: 88.26,66 88.89,66.64 88.89,68.92 89.66,69.69 JP15.10
N$179
  Top 0.305: U$8.11 85.85,67.02 85.08,67.78 85.08,73.5 88.89,77.3 92.07,77.3 93.34,76.03 93.34,74.13 92.07,72.86 JP15.11
N$180
  Top 0.305: U$8.12 87.32,73.19 89.53,75.4 JP15.12
N$181
  Top 0.305: U$8.24 79.04,49.67 76.83,47.46 JP16.1
N$182
  Top 0.305: U$8.23 80.77,55.59 81.27,55.08 81.27,49.37 77.46,45.55 74.29,45.55 73.02,46.82 73.02,48.73 74.29,50 JP16.2
N$183
  Top 0.254: U$8.22 78.1,56.6
  Top 0.305: 78.1,56.6 77.46,55.97 77.46,53.94 76.7,53.17 JP16.3
N$184
  Top 0.254: U$8.21 78.1,57.87
  Top 0.305: 78.1,57.87 77.46,57.24 77.46,56.73 76.45,55.71 JP16.4
N$185
  Top 0.305: U$8.20 77.97,59.4 76.19,57.62 JP16.5
N$186
  Top 0.305: U$8.19 77.34,60.67 76.83,60.16 JP16.6
N$187
  Top 0.305: U$8.18 77.59,61.94 76.83,62.7 JP16.7
N$188
  Top 0.305: U$8.17 78.23,63.21 76.19,65.24 JP16.8
N$189
  Top 0.254: U$8.16 78.1,64.73
  Top 0.305: 78.1,64.73 77.46,65.37 77.46,65.88 JP16.9
N$190
  Top 0.254: U$8.15 78.1,66
  Top 0.305: 78.1,66 77.46,66.64 77.46,68.92 76.7,69.69 JP16.10
N$191
  Top 0.305: U$8.14 80.51,67.02 81.27,67.78 81.27,73.5 77.46,77.3 74.29,77.3 73.02,76.03 73.02,74.13 74.29,72.86
  Top 0.406: 74.29,72.86 JP16.11
N$192
  Top 0.305: U$8.13 79.04,73.19 76.83,75.4 JP16.12
(copper drawn outside any net)
  shapes: Top circle x8

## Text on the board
_tNames: JP2 | U$1 | JP1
